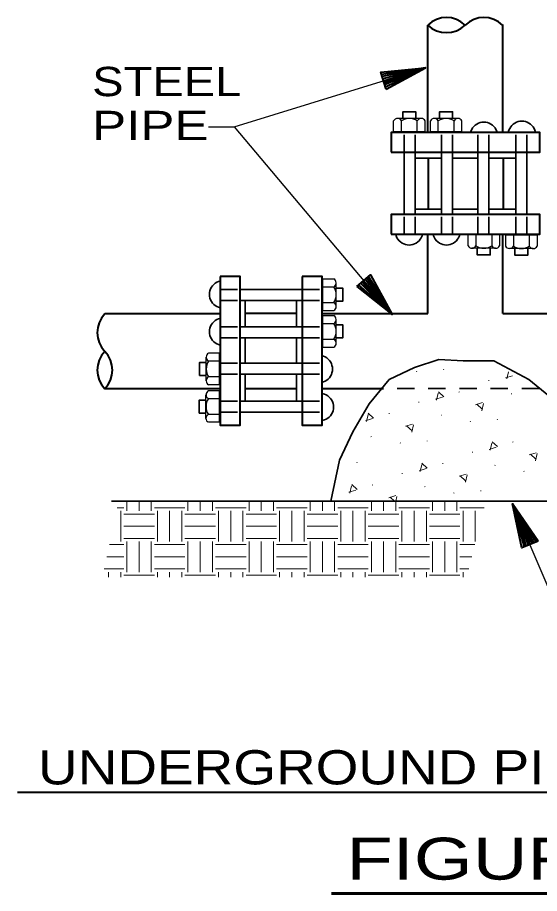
# Model space of a CAD drawing. Extents: x 55 to 190, y 198 to 264.
# Drawn here: x 91.68 to 96.19, y 222.57 to 230.16 of the extents above; entities that cross this region are included whole.
import ezdxf
from ezdxf.enums import TextEntityAlignment as Align

# ---------------------------------------------------------------- set-up
doc = ezdxf.new("R2010")
doc.units = 0
doc.header["$LTSCALE"] = 0.1
doc.linetypes.add('SHORT_DASHED', pattern=[2.7, 1.5, -1.2])
doc.layers.add('2', color=7, linetype='Continuous', lineweight=40)

msp = doc.modelspace()

# ---------------------------------------------------------------- linework, layer by layer
at = {"layer": '2'}
for p, q in [((95.2271, 229.1653), (95.2271, 230.0967)), ((95.8777, 229.1653), (95.8777, 230.1022)), ((95.2091, 229.7271), (94.8273, 229.6675)), ((95.2091, 229.7271), (94.8381, 229.6318)), ((94.8437, 229.6135), (95.2091, 229.7271)), ((95.2091, 229.7271), (94.8492, 229.5966)), ((95.2091, 229.7271), (94.8537, 229.5802)), ((95.2091, 229.7271), (94.8606, 229.5598)), ((95.231, 228.9428), (95.231, 228.5023)), ((95.8822, 228.5023), (95.8822, 228.9428)), ((95.2271, 227.5972), (95.2271, 228.2843)), ((95.8777, 227.5972), (95.8777, 228.2843)), ((94.9183, 227.5895), (94.6444, 227.8596)), ((94.9183, 227.5895), (94.658, 227.8702)), ((94.6714, 227.8818), (94.9183, 227.5895)), ((94.9183, 227.5895), (94.6863, 227.894)), ((94.9183, 227.5895), (94.7148, 227.9181)), ((94.9183, 227.5895), (94.6286, 227.8453)), ((92.4312, 227.5972), (93.4308, 227.5972)), ((94.0894, 227.5977), (93.6488, 227.5977)), ((94.3119, 227.5972), (95.2271, 227.5972)), ((95.8777, 227.5972), (96.6672, 227.5972)), ((92.4312, 226.9463), (93.4308, 226.9463)), ((93.6488, 226.9465), (94.0894, 226.9465)), ((94.3119, 226.9463), (94.8434, 226.9463)), ((96.1129, 225.5961), (95.9615, 225.9477)), ((95.9615, 225.9477), (96.1449, 225.6096)), ((95.9615, 225.9477), (96.0608, 225.5742)), ((95.9615, 225.9477), (96.0952, 225.589)), ((95.9615, 225.9477), (96.129, 225.6035)), ((95.9615, 225.9477), (96.1645, 225.6186)), ((91.6756, 223.4514), (100.4002, 223.4514))]:
    msp.add_line(p, q, dxfattribs=at)
at = {"layer": '2', "lineweight": 25}
for p, q in [((94.9318, 229.1722), (94.9318, 229.2664)), ((95.1702, 229.2878), (94.9659, 229.2878)), ((94.9998, 229.1722), (94.9998, 229.2672)), ((95.1368, 229.1722), (95.1368, 229.2672)), ((95.2046, 229.1722), (95.2046, 229.2672)), ((95.2496, 229.1722), (95.2496, 229.2664)), ((95.488, 229.2878), (95.2837, 229.2878)), ((95.3175, 229.1722), (95.3175, 229.2672)), ((95.4546, 229.1722), (95.4546, 229.2672)), ((95.5223, 229.1722), (95.5223, 229.2672)), ((93.5501, 229.214), (94.9183, 227.5895)), ((95.2046, 229.1722), (94.9318, 229.1722)), ((95.5223, 229.1722), (95.2496, 229.1722)), ((95.8483, 228.2782), (95.5755, 228.2782)), ((95.5755, 228.2782), (95.5755, 228.184)), ((95.6435, 228.2782), (95.6435, 228.1832)), ((95.7806, 228.2782), (95.7806, 228.1832)), ((95.8483, 228.2782), (95.8483, 228.1832)), ((96.174, 228.2763), (95.9012, 228.2763)), ((95.9012, 228.2763), (95.9012, 228.1821)), ((95.9692, 228.2763), (95.9692, 228.1814)), ((96.1063, 228.2763), (96.1063, 228.1814)), ((96.174, 228.2763), (96.174, 228.1814)), ((95.8139, 228.1626), (95.6097, 228.1626)), ((96.1396, 228.1607), (95.9354, 228.1607)), ((94.3188, 227.6241), (94.3188, 227.8969)), ((94.3188, 227.8969), (94.4129, 227.8969)), ((94.4344, 227.6585), (94.4344, 227.8628)), ((94.3188, 227.8289), (94.4137, 227.8289)), ((94.3188, 227.6919), (94.4137, 227.6919)), ((94.3188, 227.6241), (94.4137, 227.6241)), ((94.3188, 227.3064), (94.3188, 227.5792)), ((94.3188, 227.5792), (94.4129, 227.5792)), ((94.3188, 227.5112), (94.4137, 227.5112)), ((94.4344, 227.3408), (94.4344, 227.545)), ((94.3188, 227.3741), (94.4137, 227.3741)), ((93.4247, 227.2532), (93.3305, 227.2532)), ((93.4247, 226.9804), (93.4247, 227.2532)), ((94.3188, 227.3064), (94.4137, 227.3064)), ((93.3091, 227.0148), (93.3091, 227.2191)), ((93.4247, 227.1852), (93.3297, 227.1852)), ((93.4247, 227.0481), (93.3297, 227.0481)), ((93.4247, 226.9804), (93.3297, 226.9804)), ((93.3072, 226.6891), (93.3072, 226.8934)), ((93.4229, 226.9275), (93.3287, 226.9275)), ((93.4229, 226.6547), (93.4229, 226.9275)), ((93.4229, 226.8595), (93.3279, 226.8595)), ((93.4229, 226.7224), (93.3279, 226.7224)), ((93.4229, 226.6547), (93.3279, 226.6547))]:
    msp.add_line(p, q, dxfattribs=at)
at = {"layer": '2', "linetype": 'SHORT_DASHED', "lineweight": 35}
for p, q in [((95.0228, 228.9944), (95.0228, 229.1653)), ((95.1173, 228.9944), (95.1173, 229.1653)), ((95.3461, 228.9944), (95.3461, 229.1653)), ((95.4406, 228.9944), (95.4406, 229.1653)), ((95.6613, 228.9944), (95.6613, 229.1653)), ((95.7557, 228.9944), (95.7557, 229.1653)), ((95.9906, 228.9944), (95.9906, 229.1653)), ((96.0851, 228.9944), (96.0851, 229.1653)), ((95.0228, 228.2848), (95.0228, 228.4557)), ((95.1173, 228.2848), (95.1173, 228.4557)), ((95.3461, 228.2848), (95.3461, 228.4557)), ((95.4406, 228.2848), (95.4406, 228.4557)), ((95.6613, 228.2848), (95.6613, 228.4557)), ((95.7557, 228.2848), (95.7557, 228.4557)), ((95.9906, 228.2848), (95.9906, 228.4557)), ((96.0851, 228.2848), (96.0851, 228.4557)), ((93.4313, 227.8059), (93.6023, 227.8059)), ((94.141, 227.8059), (94.3119, 227.8059)), ((93.4313, 227.7115), (93.6023, 227.7115)), ((94.141, 227.7115), (94.3119, 227.7115)), ((93.4313, 227.4826), (93.6023, 227.4826)), ((94.141, 227.4826), (94.3119, 227.4826)), ((93.4313, 227.3881), (93.6023, 227.3881)), ((94.141, 227.3881), (94.3119, 227.3881)), ((93.4313, 227.1675), (93.6023, 227.1675)), ((94.141, 227.1675), (94.3119, 227.1675)), ((93.4313, 227.073), (93.6023, 227.073)), ((94.141, 227.073), (94.3119, 227.073)), ((96.1917, 226.9463), (94.8434, 226.9463)), ((93.4313, 226.8381), (93.6023, 226.8381)), ((94.141, 226.8381), (94.3119, 226.8381)), ((93.4313, 226.7436), (93.6023, 226.7436)), ((94.141, 226.7436), (94.3119, 226.7436))]:
    msp.add_line(p, q, dxfattribs=at)
at = {"layer": '2', "lineweight": 35}
for p, q in [((95.0228, 228.4552), (95.0228, 228.9944)), ((95.1173, 228.4552), (95.1173, 228.9944)), ((95.3461, 228.4552), (95.3461, 228.9944)), ((95.4406, 228.4552), (95.4406, 228.9944)), ((95.6613, 228.9944), (95.6613, 228.4552)), ((95.7557, 228.9944), (95.7557, 228.4552)), ((95.9906, 228.9944), (95.9906, 228.4552)), ((96.0851, 228.9944), (96.0851, 228.4552)), ((95.3453, 228.9431), (95.1173, 228.9431)), ((95.6615, 228.9431), (95.4403, 228.9431)), ((95.9906, 228.9431), (95.7565, 228.9431)), ((95.1173, 228.5007), (95.3453, 228.5007)), ((95.4403, 228.5007), (95.6615, 228.5007)), ((95.7565, 228.5007), (95.9906, 228.5007)), ((93.6017, 227.8059), (94.141, 227.8059)), ((93.6017, 227.7115), (94.141, 227.7115)), ((93.6472, 227.7115), (93.6472, 227.4834)), ((94.0896, 227.4834), (94.0896, 227.7115)), ((93.6017, 227.4826), (94.141, 227.4826)), ((93.6017, 227.3881), (94.141, 227.3881)), ((93.6472, 227.3884), (93.6472, 227.1672)), ((94.0896, 227.1672), (94.0896, 227.3884)), ((94.141, 227.1675), (93.6017, 227.1675)), ((94.141, 227.073), (93.6017, 227.073)), ((93.6472, 227.0722), (93.6472, 226.8381)), ((94.0896, 226.8381), (94.0896, 227.0722)), ((94.141, 226.8381), (93.6017, 226.8381)), ((94.141, 226.7436), (93.6017, 226.7436)), ((92.4897, 225.9702), (98.8931, 225.9702))]:
    msp.add_line(p, q, dxfattribs=at)
at = {"layer": '2', "lineweight": 13}
for p, q in [((95.1339, 227.0934), (95.1302, 227.0968)), ((95.3652, 227.1143), (95.3641, 227.1093)), ((95.925, 227.0921), (95.911, 227.0317)), ((95.7562, 227.0132), (95.7573, 227.0185)), ((95.9015, 227.0397), (95.9621, 227.0582)), ((95.294, 226.8539), (95.3549, 226.8727)), ((95.3175, 226.9082), (95.3033, 226.8463)), ((95.3662, 226.8767), (95.3199, 226.9201)), ((95.4967, 226.9159), (95.5025, 226.9177)), ((95.9544, 226.9024), (95.9494, 226.901)), ((95.1485, 226.8277), (95.1498, 226.8328)), ((95.7015, 226.8251), (95.6406, 226.8066)), ((95.652, 226.8108), (95.6986, 226.7677)), ((95.6967, 226.7555), (95.711, 226.8174)), ((94.7101, 226.7227), (94.6958, 226.6608)), ((94.7588, 226.6907), (94.7122, 226.7341)), ((94.8892, 226.7304), (94.8953, 226.7322)), ((95.3472, 226.7169), (95.3422, 226.7153)), ((94.6868, 226.6685), (94.7476, 226.687)), ((95.0943, 226.6394), (95.0334, 226.6208)), ((95.5985, 226.6603), (95.5946, 226.664)), ((95.8301, 226.6812), (95.829, 226.6761)), ((95.0445, 226.6248), (95.0911, 226.5817)), ((95.089, 226.57), (95.1032, 226.6317)), ((94.74, 226.5311), (94.7349, 226.5296)), ((95.2226, 226.4957), (95.2213, 226.4904)), ((95.8306, 226.4438), (95.7843, 226.487)), ((95.961, 226.4825), (95.9671, 226.4843)), ((94.9911, 226.4743), (94.9871, 226.478)), ((95.7586, 226.4206), (95.8195, 226.4391)), ((95.7824, 226.4751), (95.7681, 226.4131)), ((95.6134, 226.3946), (95.6144, 226.3997)), ((96.1658, 226.3917), (96.1052, 226.3732)), ((96.1166, 226.3777), (96.1629, 226.3346)), ((96.1613, 226.3224), (96.1756, 226.3843)), ((94.6148, 226.3102), (94.6135, 226.3049)), ((95.1749, 226.2893), (95.1607, 226.2277)), ((95.2231, 226.2578), (95.1768, 226.301)), ((95.3538, 226.2967), (95.3599, 226.2986)), ((95.8118, 226.2832), (95.8065, 226.2819)), ((95.0056, 226.2089), (95.0069, 226.2142)), ((95.1514, 226.2351), (95.2123, 226.2536)), ((95.5586, 226.206), (95.498, 226.1875)), ((95.5091, 226.192), (95.5554, 226.1485)), ((95.5538, 226.1367), (95.5681, 226.1986)), ((96.0629, 226.2271), (96.0589, 226.2308)), ((94.6156, 226.0718), (94.5691, 226.1152)), ((94.7466, 226.1112), (94.7527, 226.1131)), ((94.5442, 226.0493), (94.6048, 226.0679)), ((94.5672, 226.1038), (94.5529, 226.0419)), ((95.2043, 226.0978), (95.1993, 226.0962)), ((95.4554, 226.0411), (95.4514, 226.0448)), ((95.6872, 226.0626), (95.6861, 226.0573)), ((92.622, 225.8866), (92.622, 225.9737)), ((92.7278, 225.8866), (92.7278, 225.9737)), ((92.8337, 225.8866), (92.8337, 225.9737)), ((93.1511, 225.8866), (93.1511, 225.9737)), ((93.257, 225.8866), (93.257, 225.9737)), ((93.3628, 225.8866), (93.3628, 225.9737)), ((93.6803, 225.8866), (93.6803, 225.9737)), ((93.7861, 225.8866), (93.7861, 225.9737)), ((93.892, 225.8866), (93.892, 225.9737)), ((94.2095, 225.8866), (94.2095, 225.9737)), ((94.3153, 225.8866), (94.3153, 225.9737)), ((94.4212, 225.8866), (94.4212, 225.9737)), ((94.7387, 225.8866), (94.7387, 225.9737)), ((94.8445, 225.8866), (94.8445, 225.9737)), ((94.9514, 226.0202), (94.8908, 226.0017)), ((94.9014, 226.006), (94.9397, 225.9702)), ((94.9503, 225.8866), (94.9503, 225.9737)), ((94.9506, 225.9702), (94.9604, 226.0131)), ((95.2678, 225.8866), (95.2678, 225.9737)), ((95.3737, 225.8866), (95.3737, 225.9737)), ((95.4795, 225.8866), (95.4795, 225.9737)), ((92.5373, 225.9131), (92.5955, 225.9131)), ((92.5691, 225.622), (92.5691, 225.8866)), ((92.8601, 225.9131), (93.1247, 225.9131)), ((92.8866, 225.622), (92.8866, 225.8866)), ((92.9924, 225.622), (92.9924, 225.8866)), ((93.0982, 225.622), (93.0982, 225.8866)), ((93.3893, 225.9131), (93.6539, 225.9131)), ((93.4157, 225.622), (93.4157, 225.8866)), ((93.5216, 225.622), (93.5216, 225.8866)), ((93.6274, 225.622), (93.6274, 225.8866)), ((93.9184, 225.9131), (94.183, 225.9131)), ((93.9449, 225.622), (93.9449, 225.8866)), ((94.0507, 225.622), (94.0507, 225.8866)), ((94.1566, 225.622), (94.1566, 225.8866)), ((94.4476, 225.9131), (94.7122, 225.9131)), ((94.4741, 225.622), (94.4741, 225.8866)), ((94.5799, 225.622), (94.5799, 225.8866)), ((94.6857, 225.622), (94.6857, 225.8866)), ((94.9768, 225.9131), (95.2414, 225.9131)), ((95.0032, 225.622), (95.0032, 225.8866)), ((95.1091, 225.622), (95.1091, 225.8866)), ((95.2149, 225.622), (95.2149, 225.8866)), ((95.5059, 225.9131), (95.7155, 225.9131)), ((95.5324, 225.622), (95.5324, 225.8866)), ((95.6382, 225.622), (95.6382, 225.8866)), ((92.5955, 225.8602), (92.8601, 225.8602)), ((93.1247, 225.8602), (93.3893, 225.8602)), ((93.6539, 225.8602), (93.9184, 225.8602)), ((94.183, 225.8602), (94.4476, 225.8602)), ((94.7122, 225.8602), (94.9768, 225.8602)), ((95.2414, 225.8602), (95.5059, 225.8602)), ((92.5955, 225.7543), (92.8601, 225.7543)), ((93.1247, 225.7543), (93.3893, 225.7543)), ((93.6539, 225.7543), (93.9184, 225.7543)), ((94.183, 225.7543), (94.4476, 225.7543)), ((94.7122, 225.7543), (94.9768, 225.7543)), ((95.2414, 225.7543), (95.5059, 225.7543)), ((92.4709, 225.5956), (92.5955, 225.5956)), ((92.5955, 225.6485), (92.8601, 225.6485)), ((92.622, 225.3575), (92.622, 225.622)), ((92.7278, 225.3575), (92.7278, 225.622)), ((92.8337, 225.3575), (92.8337, 225.622)), ((92.8601, 225.5956), (93.1247, 225.5956)), ((93.1247, 225.6485), (93.3893, 225.6485)), ((93.1511, 225.3575), (93.1511, 225.622)), ((93.257, 225.3575), (93.257, 225.622)), ((93.3628, 225.3575), (93.3628, 225.622)), ((93.3893, 225.5956), (93.6539, 225.5956)), ((93.6539, 225.6485), (93.9184, 225.6485)), ((93.6803, 225.3575), (93.6803, 225.622)), ((93.7861, 225.3575), (93.7861, 225.622)), ((93.892, 225.3575), (93.892, 225.622)), ((93.9184, 225.5956), (94.183, 225.5956)), ((94.183, 225.6485), (94.4476, 225.6485)), ((94.2095, 225.3575), (94.2095, 225.622)), ((94.3153, 225.3575), (94.3153, 225.622)), ((94.4212, 225.3575), (94.4212, 225.622)), ((94.4476, 225.5956), (94.7122, 225.5956)), ((94.7122, 225.6485), (94.9768, 225.6485)), ((94.7387, 225.3575), (94.7387, 225.622)), ((94.8445, 225.3575), (94.8445, 225.622)), ((94.9503, 225.3575), (94.9503, 225.622)), ((94.9768, 225.5956), (95.2414, 225.5956)), ((95.2414, 225.6485), (95.5059, 225.6485)), ((95.2678, 225.3575), (95.2678, 225.622)), ((95.3737, 225.3575), (95.3737, 225.622)), ((95.4795, 225.3575), (95.4795, 225.622)), ((95.5059, 225.5956), (95.6361, 225.5956)), ((92.4487, 225.4897), (92.5955, 225.4897)), ((92.8601, 225.4897), (93.1247, 225.4897)), ((93.3893, 225.4897), (93.6539, 225.4897)), ((93.9184, 225.4897), (94.183, 225.4897)), ((94.4476, 225.4897), (94.7122, 225.4897)), ((94.9768, 225.4897), (95.2414, 225.4897)), ((95.5059, 225.4897), (95.6097, 225.4897)), ((92.4265, 225.3839), (92.5955, 225.3839)), ((92.4632, 225.313), (92.4632, 225.3575)), ((92.5691, 225.313), (92.5691, 225.3575)), ((92.8601, 225.3839), (93.1247, 225.3839)), ((92.8866, 225.313), (92.8866, 225.3575)), ((92.9924, 225.313), (92.9924, 225.3575)), ((93.0982, 225.313), (93.0982, 225.3575)), ((93.3893, 225.3839), (93.6539, 225.3839)), ((93.4157, 225.313), (93.4157, 225.3575)), ((93.5216, 225.313), (93.5216, 225.3575)), ((93.6274, 225.313), (93.6274, 225.3575)), ((93.9184, 225.3839), (94.183, 225.3839)), ((93.9449, 225.313), (93.9449, 225.3575)), ((94.0507, 225.313), (94.0507, 225.3575)), ((94.1566, 225.313), (94.1566, 225.3575)), ((94.4476, 225.3839), (94.7122, 225.3839)), ((94.4741, 225.313), (94.4741, 225.3575)), ((94.5799, 225.313), (94.5799, 225.3575)), ((94.6857, 225.313), (94.6857, 225.3575)), ((94.9768, 225.3839), (95.2414, 225.3839)), ((95.0032, 225.313), (95.0032, 225.3575)), ((95.1091, 225.313), (95.1091, 225.3575)), ((95.2149, 225.313), (95.2149, 225.3575)), ((95.5059, 225.3839), (95.5832, 225.3839)), ((95.5324, 225.313), (95.5324, 225.3575)), ((92.5955, 225.331), (92.8601, 225.331)), ((93.1247, 225.331), (93.3893, 225.331)), ((93.6539, 225.331), (93.9184, 225.331)), ((94.183, 225.331), (94.4476, 225.331)), ((94.7122, 225.331), (94.9768, 225.331)), ((95.2414, 225.331), (95.5059, 225.331))]:
    msp.add_line(p, q, dxfattribs=at)
at = {"layer": '2', "lineweight": 60}
msp.add_line((94.3928, 222.5722), (98.043, 222.5722), dxfattribs=at)
at = {"layer": '2', "lineweight": 25}
for points in [[(93.3279, 229.214), (93.5501, 229.214), (95.2091, 229.7271)], [(96.6627, 224.9902), (96.3719, 224.9902), (95.9615, 225.9477)]]:
    msp.add_lwpolyline(points, dxfattribs=at)
at = {"layer": '2'}
for points in [[(94.8662, 229.5413), (94.8212, 229.6876), (95.2091, 229.7271)], [(94.8662, 229.5413), (95.2091, 229.7271), (94.8323, 229.6498)], [(94.6138, 227.8329), (94.731, 227.9313), (94.9183, 227.5895)], [(94.6138, 227.8329), (94.9183, 227.5895), (94.7006, 227.9065)], [(96.1822, 225.6263), (96.0415, 225.5662), (95.9615, 225.9477)], [(96.1822, 225.6263), (95.9615, 225.9477), (96.0777, 225.5813)]]:
    msp.add_lwpolyline(points, dxfattribs=at)
at = {"layer": '2', "lineweight": 35}
for points in [[(95.012, 229.2884), (95.012, 229.3458), (95.1239, 229.3458), (95.1239, 229.2884)], [(95.3297, 229.2884), (95.3297, 229.3458), (95.4416, 229.3458), (95.4416, 229.2884)], [(95.8274, 229.1653), (95.8242, 229.177), (95.8179, 229.1918), (95.8094, 229.2058), (95.7991, 229.2182), (95.7874, 229.2294), (95.7742, 229.2386), (95.7599, 229.246), (95.7446, 229.2516), (95.7287, 229.2548), (95.7126, 229.2561), (95.6964, 229.2548), (95.6806, 229.2516), (95.6652, 229.246), (95.6509, 229.2386), (95.6377, 229.2294), (95.6261, 229.2182), (95.6157, 229.2058), (95.6075, 229.1918), (95.6009, 229.177), (95.5978, 229.1653)], [(96.1592, 229.1653), (96.1536, 229.1862), (96.1473, 229.2011), (96.1388, 229.2148), (96.1285, 229.2275), (96.1169, 229.2384), (96.1036, 229.2479), (96.0893, 229.2553), (96.074, 229.2609), (96.0581, 229.264), (96.042, 229.2651), (96.0258, 229.264), (96.01, 229.2609), (95.9949, 229.2553), (95.9803, 229.2479), (95.9671, 229.2384), (95.9555, 229.2275), (95.9452, 229.2148), (95.9369, 229.2011), (95.9303, 229.1862), (95.9248, 229.1653)], [(94.9503, 228.2843), (94.9543, 228.2694), (94.9609, 228.2546), (94.9691, 228.2409), (94.9794, 228.2282), (94.9911, 228.2171), (95.0043, 228.2078), (95.0188, 228.2004), (95.0339, 228.1948), (95.0498, 228.1917), (95.0659, 228.1906), (95.0821, 228.1917), (95.098, 228.1948), (95.1133, 228.2004), (95.1276, 228.2078), (95.1408, 228.2171), (95.1525, 228.2282), (95.1628, 228.2409), (95.1712, 228.2546), (95.1776, 228.2694), (95.1816, 228.2843)], [(95.2736, 228.2843), (95.2776, 228.2694), (95.2842, 228.2546), (95.2924, 228.2409), (95.3027, 228.2282), (95.3144, 228.2171), (95.3276, 228.2078), (95.3422, 228.2004), (95.3572, 228.1948), (95.3731, 228.1917), (95.3893, 228.1906), (95.4054, 228.1917), (95.4213, 228.1948), (95.4366, 228.2004), (95.4509, 228.2078), (95.4641, 228.2171), (95.4758, 228.2282), (95.4861, 228.2409), (95.4946, 228.2546), (95.5009, 228.2694), (95.5049, 228.2843)], [(95.6557, 228.162), (95.6557, 228.1046), (95.7676, 228.1046), (95.7676, 228.162)], [(95.9814, 228.1602), (95.9814, 228.1028), (96.0933, 228.1028), (96.0933, 228.1602)], [(93.4308, 227.8784), (93.416, 227.8744), (93.4012, 227.8678), (93.3874, 227.8596), (93.3747, 227.8493), (93.3636, 227.8377), (93.3544, 227.8244), (93.3469, 227.8099), (93.3414, 227.7948), (93.3382, 227.7789), (93.3372, 227.7628), (93.3382, 227.7466), (93.3414, 227.7308), (93.3469, 227.7154), (93.3544, 227.7011), (93.3636, 227.6879), (93.3747, 227.6763), (93.3874, 227.6659), (93.4012, 227.6575), (93.416, 227.6511), (93.4308, 227.6472)], [(94.4349, 227.8167), (94.4923, 227.8167), (94.4923, 227.7048), (94.4349, 227.7048)], [(93.4308, 227.5551), (93.416, 227.5511), (93.4012, 227.5445), (93.3874, 227.5363), (93.3747, 227.526), (93.3636, 227.5143), (93.3544, 227.5011), (93.3469, 227.4866), (93.3414, 227.4715), (93.3382, 227.4556), (93.3372, 227.4394), (93.3382, 227.4233), (93.3414, 227.4074), (93.3469, 227.3921), (93.3544, 227.3778), (93.3636, 227.3646), (93.3747, 227.3529), (93.3874, 227.3426), (93.4012, 227.3342), (93.416, 227.3278), (93.4308, 227.3238)], [(94.4349, 227.499), (94.4923, 227.499), (94.4923, 227.3871), (94.4349, 227.3871)], [(93.3086, 227.173), (93.2512, 227.173), (93.2512, 227.0611), (93.3086, 227.0611)], [(94.3119, 227.0013), (94.3235, 227.0045), (94.3383, 227.0108), (94.3524, 227.0193), (94.3648, 227.0296), (94.3759, 227.0413), (94.3852, 227.0545), (94.3926, 227.0688), (94.3981, 227.0841), (94.4013, 227.1), (94.4026, 227.1161), (94.4013, 227.1323), (94.3981, 227.1482), (94.3926, 227.1635), (94.3852, 227.1778), (94.3759, 227.191), (94.3648, 227.2027), (94.3524, 227.213), (94.3383, 227.2212), (94.3235, 227.2278), (94.3119, 227.231)], [(96.6712, 225.9787), (96.5667, 226.3155), (96.4852, 226.5132), (96.369, 226.6875), (96.2761, 226.8852), (96.1018, 227.0246), (95.7996, 227.1873), (95.5324, 227.1873), (95.3231, 227.1987), (95.1138, 227.1291), (94.8932, 227.0246), (94.7188, 226.8153), (94.5794, 226.5714), (94.4632, 226.3272), (94.3891, 225.9702)], [(94.3119, 226.6695), (94.3328, 226.6751), (94.3476, 226.6814), (94.3614, 226.6899), (94.3741, 226.7002), (94.3849, 226.7118), (94.3944, 226.7251), (94.4018, 226.7394), (94.4074, 226.7547), (94.4106, 226.7706), (94.4116, 226.7867), (94.4106, 226.8029), (94.4074, 226.8188), (94.4018, 226.8338), (94.3944, 226.8484), (94.3849, 226.8616), (94.3741, 226.8733), (94.3614, 226.8836), (94.3476, 226.8918), (94.3328, 226.8984), (94.3119, 226.9039)], [(93.3067, 226.8473), (93.2493, 226.8473), (93.2493, 226.7354), (93.3067, 226.7354)]]:
    msp.add_lwpolyline(points, dxfattribs=at)
at = {"layer": '2'}
for points in [[(94.9104, 228.9944), (96.1973, 228.9944), (96.1973, 229.1653), (94.9104, 229.1653)], [(94.9104, 228.2843), (96.1973, 228.2843), (96.1973, 228.4552), (94.9104, 228.4552)], [(93.4308, 227.9183), (93.4308, 226.6314), (93.6017, 226.6314), (93.6017, 227.9183)], [(94.141, 227.9183), (94.141, 226.6314), (94.3119, 226.6314), (94.3119, 227.9183)]]:
    msp.add_lwpolyline(points, close=True, dxfattribs=at)
for centre, start, end in [((95.3891, 229.929), 45.9775, 134.02119), ((95.7132, 229.929), 45.97881, 134.0225), ((95.3891, 230.2643), 225.97881, 314.0225), ((92.5989, 227.4313), 135.97881, 224.0225), ((92.5989, 227.1073), 135.9775, 224.02119), ((92.2636, 227.1073), 315.97881, 44.0225)]:
    msp.add_arc(centre, 0.2331, start, end, dxfattribs=at)
at = {"layer": '2', "lineweight": 25}
for centre, radius, start, end in [((94.9661, 229.2494), 0.0382, 28.1609, 153.21731), ((95.0684, 229.1618), 0.126, 57.05703, 122.99384), ((95.1707, 229.2497), 0.0382, 27.96581, 152.1123), ((95.2838, 229.2494), 0.0382, 28.1609, 153.21731), ((95.3861, 229.1618), 0.126, 57.05703, 122.99384), ((95.4884, 229.2497), 0.0382, 27.96581, 152.1123), ((95.6098, 228.201), 0.0382, 206.78269, 331.8391), ((95.7121, 228.2886), 0.126, 237.00616, 302.94298), ((95.8144, 228.2007), 0.0382, 207.8877, 332.03419), ((95.9355, 228.1991), 0.0382, 206.78269, 331.8391), ((96.0378, 228.2867), 0.126, 237.00616, 302.94298), ((96.1401, 228.1988), 0.0382, 207.8877, 332.03419), ((94.396, 227.8626), 0.0382, 298.1609, 63.21731), ((94.3084, 227.7603), 0.126, 327.05703, 32.99384), ((94.3963, 227.6581), 0.0382, 297.96581, 62.1123), ((94.396, 227.5449), 0.0382, 298.1609, 63.21731), ((94.3084, 227.4426), 0.126, 327.05703, 32.99384), ((94.3963, 227.3403), 0.0382, 297.96581, 62.1123), ((93.3475, 227.2189), 0.0382, 116.78269, 241.8391), ((93.4351, 227.1166), 0.126, 147.00616, 212.94297), ((93.3472, 227.0143), 0.0382, 117.8877, 242.03419), ((93.3457, 226.8932), 0.0382, 116.78269, 241.8391), ((93.4333, 226.7909), 0.126, 147.00616, 212.94297), ((93.3454, 226.6886), 0.0382, 117.8877, 242.03419)]:
    msp.add_arc(centre, radius, start, end, dxfattribs=at)

# ---------------------------------------------------------------- texts
at = {"layer": '2'}
for s, width, p in [('STEEL', 1.2, (92.3217, 229.4807)), ('PIPE', 1.3, (92.3217, 229.0997))]:
    msp.add_text(s, height=0.254, dxfattribs=dict(at, width=width)).set_placement(p)
for s, height, width, p in [('UNDERGROUND PIPING RISER-TEES', 0.2963, 1.2, (96.1193, 223.5173)), ('FIGURE "M"', 0.3633, 1.35, (96.3596, 222.6923))]:
    msp.add_text(s, height=height, dxfattribs=dict(at, width=width)).set_placement(p, align=Align.CENTER)

doc.saveas('drawing.dxf')
